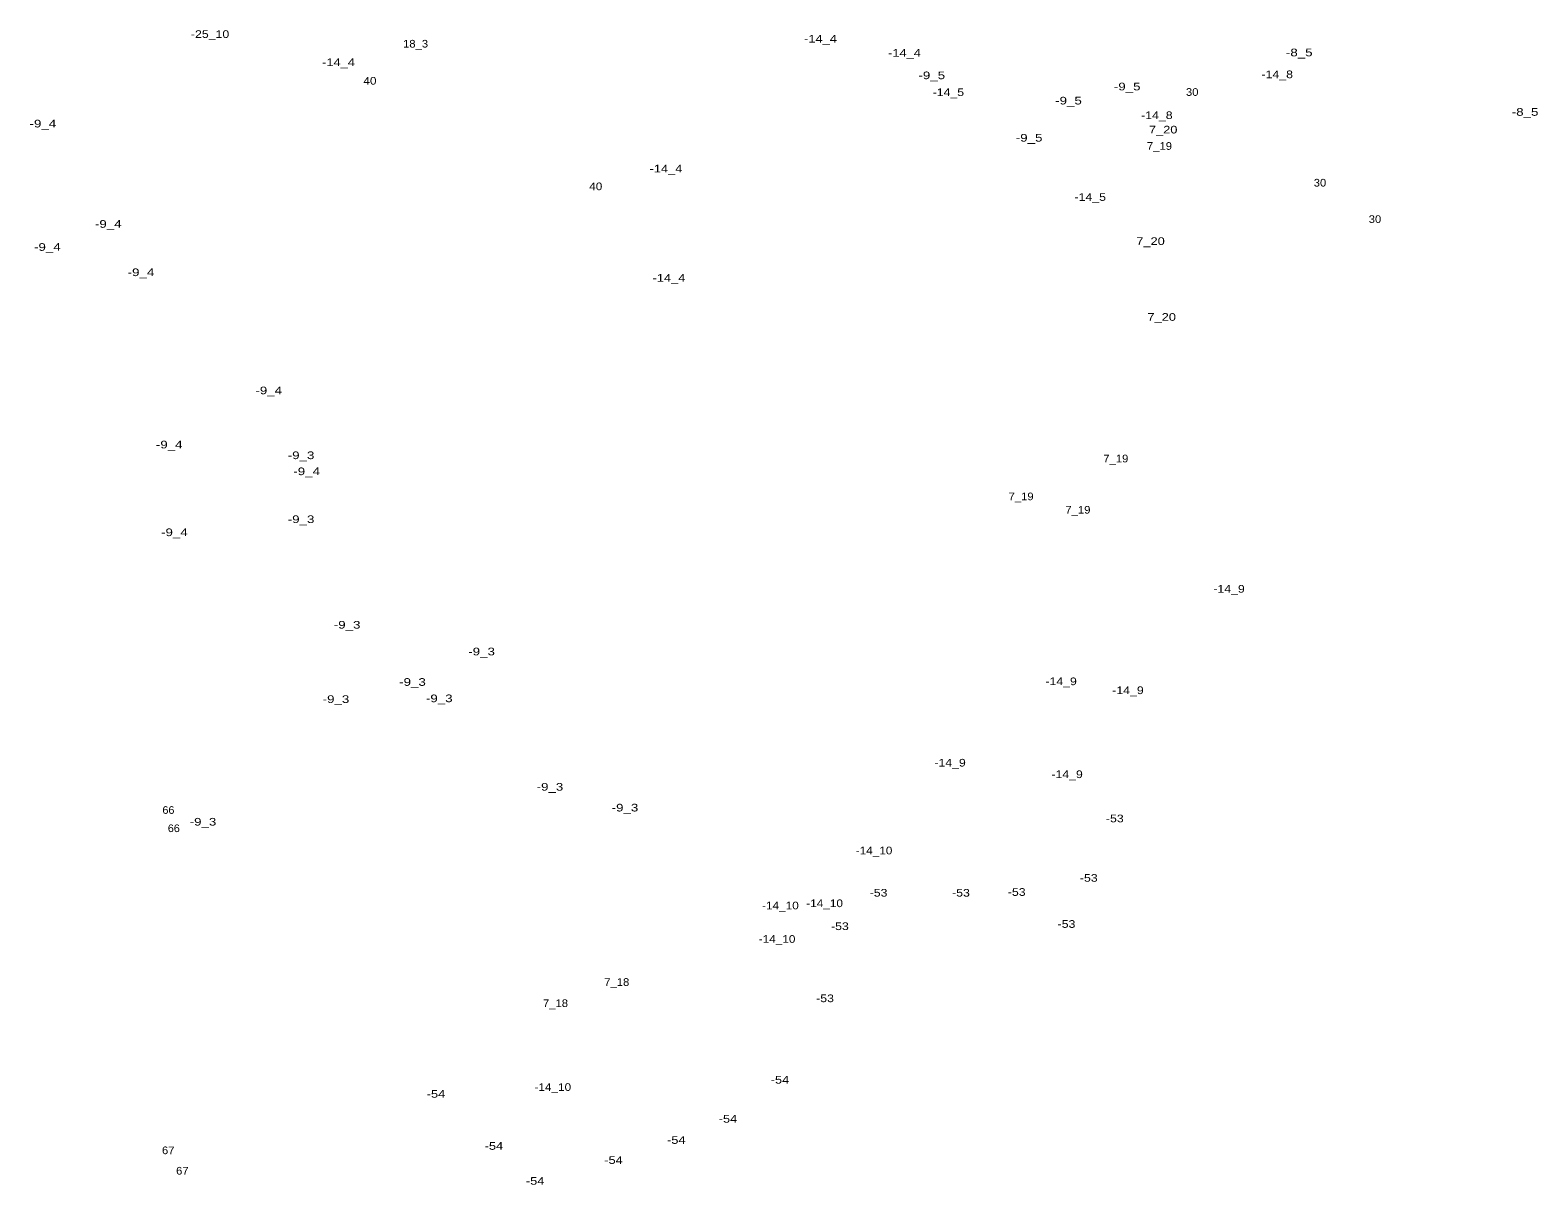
# Model space of a CAD drawing. Extents: x -663705 to -661666, y -1002081 to -999269.
# Drawn here: x -662453 to -661666, y -1001795 to -1001193 of the extents above; entities that cross this region are included whole.
import ezdxf
from ezdxf.enums import TextEntityAlignment as Align

# ---------------------------------------------------------------- set-up
doc = ezdxf.new("R2010")
doc.units = 0
doc.header["$LTSCALE"] = 1.6
doc.layers.add('24', color=7, linetype='Continuous')

msp = doc.modelspace()

# ---------------------------------------------------------------- texts
at = {"layer": '24'}
for s, width, p in [('-25_10', 1.2, (-662358.88, -1001196.58)), ('18_3', 1.1, (-662251.64, -1001201.6)), ('-14_4', 1.25, (-662040.3, -1001199.01)), ('-14_4', 1.25, (-661996.48, -1001206.38)), ('-8_5', 1.3, (-661790.449, -1001206.17)), ('-14_4', 1.25, (-662291.86, -1001211.29)), ('-9_5', 1.3, (-661982.22, -1001218.11)), ('-14_8', 1.2, (-661801.919, -1001217.58)), ('40', 1.15, (-662275.459, -1001220.94)), ('-9_5', 1.3, (-661880.24, -1001223.93)), ('30', 1.1, (-661846.309, -1001226.8)), ('-14_5', 1.2, (-661973.569, -1001226.91)), ('-9_5', 1.3, (-661910.87, -1001231.3)), ('-14_8', 1.2, (-661864.74, -1001238.91)), ('-8_5', 1.3, (-661672.579, -1001237.2)), ('-9_4', 1.3, (-662446.14, -1001243.28)), ('7_20', 1.25, (-661861.459, -1001246.43)), ('-9_5', 1.3, (-661931.42, -1001250.69)), ('7_19', 1.1, (-661863.4, -1001254.96)), ('-14_4', 1.25, (-662120.95, -1001266.76)), ('40', 1.15, (-662157.59, -1001276.02)), ('-14_5', 1.2, (-661899.51, -1001281.6)), ('30', 1.1, (-661779.62, -1001274.13)), ('-9_4', 1.3, (-662412.02, -1001295.64)), ('30', 1.1, (-661750.919, -1001293.13)), ('7_20', 1.25, (-661868.049, -1001304.61)), ('-9_4', 1.3, (-662443.81, -1001307.67)), ('-9_4', 1.3, (-662394.96, -1001320.86)), ('-14_4', 1.25, (-662119.39, -1001323.78)), ('7_20', 1.25, (-661862.23, -1001344.18)), ('-9_4', 1.3, (-662328.27, -1001382.53)), ('-9_4', 1.3, (-662380.22, -1001410.77)), ('-9_3', 1.3, (-662311.4, -1001416.37)), ('7_19', 1.1, (-661886.181, -1001418.05)), ('-9_4', 1.3, (-662308.49, -1001424.73)), ('7_19', 1.1, (-661935.611, -1001437.82)), ('7_19', 1.1, (-661905.951, -1001444.8)), ('-9_3', 1.3, (-662311.4, -1001449.73)), ('-9_4', 1.3, (-662377.51, -1001456.54)), ('-14_9', 1.2, (-661827.09, -1001486.06)), ('-9_3', 1.3, (-662287.36, -1001504.81)), ('-9_3', 1.3, (-662217.18, -1001518.77)), ('-9_3', 1.3, (-662253.24, -1001534.67)), ('-14_9', 1.2, (-661914.72, -1001534.32)), ('-14_9', 1.2, (-661879.82, -1001538.98)), ('-9_3', 1.3, (-662293.18, -1001543.6)), ('-9_3', 1.3, (-662239.28, -1001543.21)), ('-14_9', 1.2, (-661972.69, -1001576.8)), ('-14_9', 1.2, (-661911.62, -1001582.81)), ('-9_3', 1.3, (-662181.51, -1001589.36)), ('66', 1.05, (-662380.62, -1001601.49)), ('-9_3', 1.3, (-662142.35, -1001600.23)), ('66', 1.05, (-662377.81, -1001610.99)), ('-9_3', 1.3, (-662362.58, -1001607.6)), ('-53', 1.2, (-661886.7, -1001605.87)), ('-14_10', 1.15, (-662012.36, -1001622.6)), ('-53', 1.2, (-661900.28, -1001636.9)), ('-14_10', 1.15, (-662061.22, -1001651.3)), ('-14_10', 1.15, (-662038.15, -1001650.14)), ('-53', 1.2, (-662010.01, -1001644.66)), ('-53', 1.2, (-661966.97, -1001644.66)), ('-53', 1.2, (-661937.89, -1001644.27)), ('-53', 1.2, (-662030.17, -1001662.12)), ('-53', 1.2, (-661911.91, -1001660.95)), ('-14_10', 1.15, (-662062.959, -1001668.76)), ('7_18', 1.1, (-662146.63, -1001691.23)), ('7_18', 1.1, (-662178.61, -1001702.28)), ('-53', 1.2, (-662037.93, -1001699.74)), ('-14_10', 1.15, (-662180.02, -1001746.06)), ('-54', 1.25, (-662061.47, -1001742.25)), ('-54', 1.25, (-662240.99, -1001749.62)), ('-54', 1.25, (-662088.61, -1001762.62)), ('-54', 1.25, (-662210.75, -1001776.78)), ('-54', 1.25, (-662115.56, -1001773.67)), ('67', 1.1, (-662380.72, -1001779.06)), ('-54', 1.25, (-662148.33, -1001784.15)), ('67', 1.1, (-662373.35, -1001789.72)), ('-54', 1.25, (-662189.23, -1001795.01))]:
    msp.add_text(s, height=4, dxfattribs=dict(at, width=width)).set_placement(p, align=Align.CENTER)

doc.saveas('drawing.dxf')
